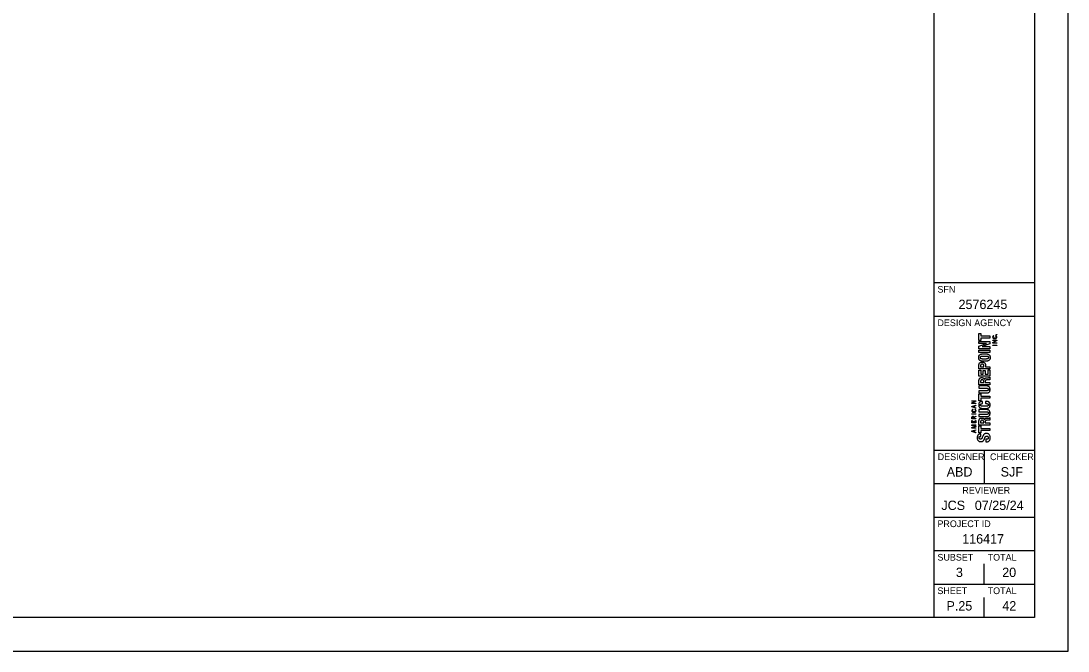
# Model space of a CAD drawing. Extents: x 0 to 34, y 0 to 22.
# Drawn here: x 18.37 to 34, y 0 to 9.41 of the extents above; entities that cross this region are included whole.
import ezdxf

# ---------------------------------------------------------------- set-up
doc = ezdxf.new("R2010")
doc.units = 0
for name, color, linetype in [('SH_Border', 7, 'Continuous'), ('SH_Cut_Line', 7, 'Continuous'), ('SH_Data', 7, 'Continuous')]:
    doc.layers.add(name, color=color, linetype=linetype)

msp = doc.modelspace()

# ---------------------------------------------------------------- linework, layer by layer
at = {"layer": 'SH_Border'}
for p, q in [((32, 0.5), (32, 21.5)), ((32, 5.5), (33.5, 5.5)), ((32, 5), (33.5, 5)), ((32, 3), (33.5, 3)), ((32.75, 3), (32.75, 2.5)), ((32, 2.5), (33.5, 2.5)), ((32, 2), (33.5, 2)), ((32, 1.5), (33.5, 1.5)), ((32, 1), (33.5, 1))]:
    msp.add_line(p, q, dxfattribs=at)
msp.add_lwpolyline([(1.5, 21.5), (33.5, 21.5), (33.5, 0.5), (1.5, 0.5)], close=True, dxfattribs=at)
at = {"layer": 'SH_Cut_Line'}
msp.add_lwpolyline([(0, 0), (34, 0), (34, 22), (0, 22)], close=True, dxfattribs=at)
at = {"layer": 'SH_Data'}
for p, q in [((32.75, 4), (32.75, 4)), ((32.75, 4), (32.75, 4)), ((32.75, 1), (32.75, 1.3)), ((32.75, 0.5), (32.75, 0.8)), ((32.375, 0.675), (32.375, 0.675))]:
    msp.add_line(p, q, dxfattribs=at)
for points in [[(32.67, 4.739), (32.697, 4.739), (32.697, 4.704), (32.833, 4.704), (32.833, 4.671), (32.697, 4.671), (32.697, 4.635), (32.67, 4.635), (32.67, 4.739)], [(32.935, 4.718), (32.927, 4.718), (32.927, 4.725), (32.935, 4.725), (32.935, 4.718)], [(32.67, 4.551), (32.781, 4.591), (32.781, 4.592), (32.67, 4.592), (32.67, 4.622), (32.833, 4.622), (32.833, 4.584), (32.719, 4.544), (32.719, 4.544), (32.833, 4.544), (32.833, 4.513), (32.67, 4.513), (32.67, 4.551)], [(32.875, 4.596), (32.875, 4.605), (32.925, 4.634), (32.925, 4.634), (32.875, 4.634), (32.875, 4.639), (32.935, 4.639), (32.935, 4.634), (32.88, 4.602), (32.88, 4.601), (32.935, 4.601), (32.935, 4.596), (32.875, 4.596)], [(32.875, 4.561), (32.875, 4.567), (32.935, 4.567), (32.935, 4.561), (32.875, 4.561)], [(32.833, 4.457), (32.67, 4.457), (32.67, 4.49), (32.833, 4.49), (32.833, 4.457)], [(32.833, 4.212), (32.67, 4.212), (32.67, 4.269)], [(32.694, 4.244), (32.743, 4.244), (32.743, 4.259)], [(32.694, 4.258), (32.694, 4.244)], [(32.768, 4.262), (32.768, 4.244), (32.833, 4.244), (32.833, 4.212)], [(32.67, 4.194), (32.697, 4.194), (32.697, 4.135), (32.735, 4.135), (32.735, 4.19), (32.762, 4.19), (32.762, 4.135), (32.806, 4.135), (32.806, 4.196), (32.833, 4.196), (32.833, 4.103), (32.67, 4.103), (32.67, 4.194)], [(32.832, 4.087), (32.833, 4.087), (32.833, 4.052)], [(32.833, 3.976), (32.67, 3.976), (32.67, 4.037)], [(32.694, 4.025), (32.694, 4.009)], [(32.694, 4.009), (32.741, 4.009), (32.741, 4.023)], [(32.752, 4.054), (32.752, 4.054)], [(32.764, 4.027), (32.764, 4.009), (32.833, 4.009), (32.833, 3.976)], [(32.816, 4.048), (32.784, 4.047)], [(32.67, 3.841), (32.697, 3.841), (32.697, 3.805), (32.833, 3.805), (32.833, 3.773), (32.697, 3.773), (32.697, 3.737), (32.67, 3.737), (32.67, 3.841)], [(32.565, 3.694), (32.565, 3.703), (32.615, 3.731), (32.615, 3.731), (32.565, 3.731), (32.565, 3.737), (32.625, 3.737), (32.625, 3.731), (32.569, 3.699), (32.569, 3.699), (32.625, 3.699), (32.625, 3.694), (32.565, 3.694)], [(32.625, 3.625), (32.565, 3.644), (32.565, 3.652), (32.625, 3.671), (32.625, 3.665), (32.605, 3.659), (32.605, 3.637), (32.625, 3.631), (32.625, 3.625)], [(32.601, 3.638), (32.601, 3.658), (32.569, 3.648), (32.569, 3.648), (32.601, 3.638)], [(32.565, 3.534), (32.565, 3.539), (32.625, 3.539), (32.625, 3.534), (32.565, 3.534)], [(32.596, 3.492), (32.625, 3.506), (32.625, 3.5), (32.597, 3.487), (32.597, 3.471), (32.625, 3.471), (32.625, 3.466), (32.565, 3.466), (32.565, 3.486)], [(32.625, 3.407), (32.565, 3.407), (32.565, 3.441), (32.569, 3.441), (32.569, 3.413), (32.591, 3.413), (32.591, 3.433), (32.596, 3.433), (32.596, 3.413), (32.62, 3.413), (32.62, 3.443), (32.625, 3.443), (32.625, 3.407)], [(32.569, 3.471), (32.593, 3.471), (32.593, 3.486)], [(32.569, 3.486), (32.569, 3.471)], [(32.752, 3.451), (32.752, 3.451)], [(32.816, 3.444), (32.784, 3.444)], [(32.832, 3.484), (32.833, 3.484), (32.833, 3.449)], [(32.625, 3.326), (32.565, 3.326), (32.565, 3.336), (32.615, 3.352), (32.615, 3.353), (32.565, 3.369), (32.565, 3.379), (32.625, 3.379), (32.625, 3.373), (32.569, 3.373), (32.569, 3.373), (32.625, 3.355), (32.625, 3.35), (32.569, 3.332), (32.569, 3.332), (32.625, 3.332), (32.625, 3.326)], [(32.625, 3.258), (32.565, 3.277), (32.565, 3.285), (32.625, 3.304), (32.625, 3.298), (32.605, 3.292), (32.605, 3.269), (32.625, 3.263), (32.625, 3.258)], [(32.601, 3.271), (32.601, 3.291), (32.569, 3.281), (32.569, 3.281), (32.601, 3.271)], [(32.833, 3.373), (32.67, 3.373), (32.67, 3.434)], [(32.67, 3.36), (32.697, 3.36), (32.697, 3.324), (32.833, 3.324), (32.833, 3.291), (32.697, 3.291), (32.697, 3.256), (32.67, 3.256), (32.67, 3.36)], [(32.694, 3.422), (32.694, 3.406)], [(32.694, 3.406), (32.741, 3.406), (32.741, 3.42)], [(32.764, 3.424), (32.764, 3.406), (32.833, 3.406), (32.833, 3.373)]]:
    msp.add_lwpolyline(points, dxfattribs=at)
for points in [[(32.893, 4.701), (32.889, 4.699), (32.885, 4.697), (32.883, 4.695), (32.88, 4.693), (32.879, 4.69), (32.879, 4.686), (32.879, 4.683), (32.88, 4.681), (32.881, 4.678), (32.882, 4.676), (32.884, 4.675), (32.887, 4.673), (32.889, 4.672), (32.892, 4.671), (32.895, 4.67), (32.898, 4.669), (32.902, 4.669), (32.905, 4.669), (32.909, 4.669), (32.912, 4.669), (32.915, 4.67), (32.919, 4.671), (32.921, 4.672), (32.924, 4.673), (32.926, 4.675), (32.928, 4.676), (32.929, 4.679), (32.931, 4.681), (32.931, 4.684), (32.931, 4.687), (32.931, 4.689), (32.931, 4.691), (32.93, 4.693), (32.929, 4.694), (32.928, 4.696), (32.927, 4.697), (32.926, 4.698), (32.924, 4.699), (32.922, 4.7), (32.921, 4.7), (32.919, 4.701), (32.917, 4.702), (32.917, 4.702), (32.918, 4.707), (32.918, 4.707), (32.92, 4.706), (32.923, 4.705), (32.925, 4.704), (32.927, 4.703), (32.929, 4.702), (32.931, 4.7), (32.932, 4.699), (32.934, 4.697), (32.934, 4.695), (32.935, 4.692), (32.936, 4.69), (32.936, 4.687), (32.936, 4.683), (32.935, 4.68), (32.934, 4.677), (32.932, 4.674), (32.93, 4.672), (32.927, 4.67), (32.925, 4.668), (32.921, 4.666), (32.918, 4.665), (32.914, 4.664), (32.91, 4.664), (32.905, 4.664), (32.901, 4.664), (32.896, 4.664), (32.893, 4.665), (32.889, 4.666), (32.886, 4.668), (32.883, 4.67), (32.88, 4.672), (32.878, 4.674), (32.877, 4.677), (32.875, 4.68), (32.875, 4.683), (32.875, 4.687), (32.875, 4.689), (32.875, 4.692), (32.876, 4.694), (32.877, 4.696), (32.878, 4.698), (32.88, 4.699), (32.881, 4.701), (32.883, 4.702), (32.885, 4.703), (32.887, 4.704), (32.889, 4.705), (32.892, 4.706), (32.892, 4.706), (32.893, 4.701), (32.893, 4.701)], [(32.751, 4.326), (32.739, 4.326), (32.727, 4.326), (32.717, 4.328), (32.706, 4.329), (32.697, 4.331), (32.69, 4.335), (32.682, 4.339), (32.677, 4.345), (32.672, 4.352), (32.668, 4.359), (32.666, 4.369), (32.666, 4.382), (32.666, 4.394), (32.668, 4.404), (32.672, 4.411), (32.677, 4.418), (32.682, 4.424), (32.69, 4.428), (32.697, 4.432), (32.706, 4.434), (32.717, 4.436), (32.727, 4.437), (32.739, 4.437), (32.751, 4.437), (32.758, 4.437), (32.764, 4.437), (32.771, 4.437)], [(32.751, 4.359), (32.762, 4.359), (32.771, 4.359), (32.779, 4.359), (32.787, 4.36), (32.793, 4.361), (32.798, 4.363), (32.803, 4.364), (32.806, 4.367), (32.808, 4.37), (32.81, 4.373), (32.812, 4.377), (32.812, 4.382), (32.812, 4.386), (32.81, 4.39), (32.808, 4.393), (32.806, 4.396), (32.803, 4.399), (32.798, 4.4), (32.793, 4.402), (32.787, 4.403), (32.779, 4.404), (32.771, 4.404), (32.762, 4.404), (32.751, 4.404), (32.74, 4.404), (32.731, 4.404), (32.723, 4.404), (32.716, 4.403), (32.709, 4.402), (32.704, 4.4), (32.7, 4.399), (32.696, 4.396), (32.694, 4.393), (32.692, 4.39), (32.691, 4.386), (32.691, 4.382), (32.691, 4.377), (32.692, 4.373), (32.694, 4.37), (32.696, 4.367), (32.7, 4.364), (32.704, 4.363), (32.709, 4.361), (32.716, 4.36), (32.723, 4.359), (32.731, 4.359), (32.74, 4.359), (32.751, 4.359)], [(32.771, 4.437), (32.776, 4.436), (32.781, 4.436), (32.785, 4.436), (32.796, 4.434), (32.805, 4.432), (32.812, 4.428), (32.82, 4.424), (32.825, 4.418), (32.83, 4.411), (32.834, 4.404), (32.836, 4.394), (32.836, 4.382), (32.836, 4.369), (32.834, 4.359), (32.83, 4.352), (32.825, 4.345), (32.82, 4.339), (32.812, 4.335), (32.805, 4.331), (32.796, 4.329), (32.785, 4.328), (32.775, 4.326), (32.763, 4.326), (32.751, 4.326)], [(32.67, 4.269), (32.67, 4.277), (32.671, 4.284), (32.674, 4.29), (32.677, 4.296), (32.68, 4.3), (32.685, 4.304), (32.689, 4.307), (32.695, 4.31), (32.701, 4.312), (32.706, 4.313), (32.712, 4.314), (32.719, 4.314), (32.727, 4.314), (32.734, 4.313), (32.741, 4.31), (32.747, 4.308), (32.752, 4.304), (32.756, 4.3), (32.76, 4.295), (32.763, 4.29), (32.765, 4.283), (32.767, 4.277), (32.768, 4.27), (32.768, 4.262)], [(32.743, 4.259), (32.743, 4.266), (32.741, 4.271), (32.737, 4.275), (32.733, 4.279), (32.727, 4.281), (32.719, 4.281), (32.711, 4.281), (32.705, 4.279), (32.7, 4.276), (32.696, 4.272), (32.694, 4.266), (32.694, 4.258)], [(32.67, 4.037), (32.67, 4.051), (32.673, 4.062), (32.68, 4.069), (32.687, 4.077), (32.698, 4.081), (32.712, 4.081), (32.723, 4.081), (32.732, 4.079), (32.739, 4.074), (32.745, 4.07), (32.75, 4.063), (32.752, 4.054)], [(32.752, 4.054), (32.753, 4.059), (32.755, 4.064), (32.757, 4.067), (32.759, 4.071), (32.762, 4.073), (32.766, 4.075), (32.769, 4.077), (32.774, 4.078), (32.78, 4.079), (32.786, 4.08), (32.794, 4.08), (32.802, 4.08), (32.811, 4.08), (32.818, 4.081), (32.822, 4.082), (32.827, 4.082), (32.83, 4.084), (32.832, 4.087)], [(32.67, 3.885), (32.67, 3.885), (32.783, 3.885), (32.783, 3.885), (32.787, 3.885), (32.791, 3.885), (32.795, 3.886), (32.798, 3.887), (32.801, 3.888), (32.803, 3.889), (32.806, 3.89), (32.808, 3.892), (32.809, 3.895), (32.811, 3.897), (32.812, 3.901), (32.812, 3.904), (32.812, 3.908), (32.811, 3.911), (32.809, 3.914), (32.808, 3.917), (32.806, 3.918), (32.803, 3.92), (32.801, 3.921), (32.798, 3.922), (32.795, 3.923), (32.791, 3.923), (32.787, 3.924), (32.783, 3.924), (32.783, 3.924), (32.67, 3.924), (32.67, 3.924), (32.67, 3.924), (32.67, 3.957), (32.67, 3.957), (32.67, 3.957), (32.783, 3.957), (32.783, 3.957), (32.794, 3.957), (32.802, 3.955), (32.809, 3.952), (32.816, 3.949), (32.821, 3.945), (32.825, 3.941), (32.829, 3.936), (32.832, 3.93), (32.834, 3.924), (32.835, 3.918), (32.836, 3.911), (32.836, 3.904), (32.836, 3.898), (32.835, 3.891), (32.834, 3.885), (32.833, 3.879), (32.83, 3.873), (32.826, 3.868), (32.822, 3.863), (32.817, 3.86), (32.81, 3.857), (32.803, 3.854), (32.794, 3.852), (32.783, 3.852), (32.783, 3.852), (32.67, 3.852), (32.67, 3.852), (32.67, 3.852), (32.67, 3.885), (32.67, 3.885)], [(32.741, 4.023), (32.741, 4.031), (32.739, 4.037), (32.735, 4.042), (32.732, 4.046), (32.725, 4.048), (32.717, 4.048), (32.702, 4.048), (32.694, 4.04), (32.694, 4.025)], [(32.784, 4.047), (32.778, 4.046), (32.773, 4.045), (32.769, 4.042), (32.766, 4.039), (32.764, 4.034), (32.764, 4.027)], [(32.833, 4.052), (32.831, 4.05), (32.828, 4.049), (32.825, 4.049), (32.822, 4.048), (32.819, 4.048), (32.816, 4.048)], [(32.582, 3.601), (32.578, 3.6), (32.575, 3.598), (32.572, 3.595), (32.57, 3.593), (32.569, 3.59), (32.569, 3.586), (32.569, 3.583), (32.569, 3.581), (32.571, 3.579), (32.572, 3.577), (32.574, 3.575), (32.576, 3.574), (32.579, 3.572), (32.581, 3.571), (32.585, 3.57), (32.588, 3.57), (32.591, 3.569), (32.595, 3.569), (32.598, 3.569), (32.602, 3.57), (32.605, 3.57), (32.608, 3.571), (32.611, 3.572), (32.613, 3.574), (32.616, 3.575), (32.618, 3.577), (32.619, 3.579), (32.62, 3.581), (32.621, 3.584), (32.621, 3.587), (32.621, 3.589), (32.62, 3.591), (32.62, 3.593), (32.619, 3.595), (32.618, 3.596), (32.617, 3.597), (32.615, 3.598), (32.614, 3.599), (32.612, 3.6), (32.61, 3.601), (32.608, 3.602), (32.606, 3.602), (32.606, 3.602), (32.607, 3.607), (32.607, 3.607), (32.61, 3.607), (32.612, 3.606), (32.615, 3.605), (32.617, 3.604), (32.619, 3.602), (32.62, 3.601), (32.622, 3.599), (32.623, 3.597), (32.624, 3.595), (32.625, 3.593), (32.625, 3.59), (32.625, 3.587), (32.625, 3.583), (32.625, 3.58), (32.623, 3.577), (32.622, 3.574), (32.62, 3.572), (32.617, 3.57), (32.614, 3.568), (32.611, 3.567), (32.607, 3.566), (32.604, 3.565), (32.599, 3.564), (32.595, 3.564), (32.59, 3.564), (32.586, 3.565), (32.582, 3.566), (32.579, 3.567), (32.575, 3.568), (32.573, 3.57), (32.57, 3.572), (32.568, 3.574), (32.566, 3.577), (32.565, 3.58), (32.564, 3.583), (32.564, 3.587), (32.564, 3.59), (32.565, 3.592), (32.566, 3.594), (32.566, 3.596), (32.568, 3.598), (32.569, 3.599), (32.571, 3.601), (32.572, 3.602), (32.575, 3.603), (32.577, 3.604), (32.579, 3.605), (32.581, 3.606), (32.581, 3.606), (32.582, 3.601), (32.582, 3.601)], [(32.725, 3.693), (32.713, 3.693), (32.704, 3.692), (32.699, 3.689), (32.693, 3.686), (32.691, 3.681), (32.691, 3.674), (32.691, 3.67), (32.692, 3.666), (32.694, 3.663), (32.696, 3.661), (32.7, 3.659), (32.705, 3.657), (32.71, 3.656), (32.716, 3.655), (32.724, 3.654), (32.732, 3.653), (32.742, 3.653), (32.753, 3.653), (32.766, 3.653), (32.776, 3.653), (32.783, 3.654), (32.791, 3.655), (32.797, 3.656), (32.801, 3.658), (32.805, 3.66), (32.808, 3.662), (32.809, 3.665), (32.811, 3.668), (32.812, 3.671), (32.812, 3.674), (32.812, 3.677), (32.811, 3.68), (32.81, 3.682), (32.809, 3.685), (32.807, 3.687), (32.804, 3.689), (32.801, 3.691), (32.797, 3.692), (32.792, 3.693), (32.786, 3.694), (32.779, 3.695), (32.77, 3.695), (32.77, 3.695), (32.77, 3.728), (32.77, 3.728), (32.779, 3.728), (32.787, 3.727), (32.795, 3.726), (32.803, 3.724), (32.81, 3.722), (32.816, 3.718), (32.822, 3.714), (32.827, 3.709), (32.831, 3.702), (32.834, 3.696), (32.836, 3.687), (32.836, 3.676), (32.836, 3.663), (32.834, 3.654), (32.83, 3.646), (32.825, 3.639), (32.82, 3.633), (32.812, 3.629), (32.805, 3.626), (32.796, 3.623), (32.785, 3.622), (32.775, 3.621), (32.763, 3.62), (32.751, 3.62), (32.739, 3.62), (32.727, 3.621), (32.717, 3.622), (32.706, 3.623), (32.697, 3.626), (32.69, 3.629), (32.682, 3.633), (32.677, 3.639), (32.672, 3.646), (32.668, 3.654), (32.666, 3.663), (32.666, 3.676), (32.666, 3.688), (32.668, 3.697), (32.672, 3.704), (32.676, 3.71), (32.681, 3.715), (32.687, 3.719), (32.692, 3.722), (32.699, 3.724), (32.706, 3.725), (32.712, 3.726), (32.719, 3.726), (32.725, 3.726), (32.725, 3.726), (32.725, 3.693), (32.725, 3.693)], [(32.67, 3.532), (32.67, 3.532), (32.783, 3.532), (32.783, 3.532), (32.787, 3.532), (32.791, 3.533), (32.795, 3.533), (32.798, 3.534), (32.801, 3.535), (32.803, 3.536), (32.806, 3.538), (32.808, 3.54), (32.809, 3.542), (32.811, 3.545), (32.812, 3.548), (32.812, 3.552), (32.812, 3.556), (32.811, 3.559), (32.809, 3.561), (32.808, 3.564), (32.806, 3.566), (32.803, 3.567), (32.801, 3.569), (32.798, 3.57), (32.795, 3.57), (32.791, 3.571), (32.787, 3.571), (32.783, 3.571), (32.783, 3.571), (32.67, 3.571), (32.67, 3.571), (32.67, 3.571), (32.67, 3.604), (32.67, 3.604), (32.67, 3.604), (32.783, 3.604), (32.783, 3.604), (32.794, 3.604), (32.802, 3.602), (32.809, 3.6), (32.816, 3.597), (32.821, 3.593), (32.825, 3.588), (32.829, 3.583), (32.832, 3.577), (32.834, 3.571), (32.835, 3.565), (32.836, 3.558), (32.836, 3.552), (32.836, 3.545), (32.835, 3.539), (32.834, 3.532), (32.833, 3.526), (32.83, 3.521), (32.826, 3.516), (32.822, 3.511), (32.817, 3.507), (32.81, 3.504), (32.803, 3.501), (32.794, 3.5), (32.783, 3.5), (32.783, 3.5), (32.67, 3.5), (32.67, 3.5), (32.67, 3.5), (32.67, 3.532), (32.67, 3.532)], [(32.565, 3.486), (32.565, 3.492), (32.566, 3.496), (32.569, 3.499), (32.572, 3.503), (32.576, 3.504), (32.581, 3.504), (32.585, 3.504), (32.588, 3.503), (32.591, 3.501), (32.593, 3.499), (32.595, 3.496), (32.596, 3.492)], [(32.593, 3.486), (32.593, 3.49), (32.592, 3.493), (32.59, 3.495), (32.588, 3.497), (32.585, 3.499), (32.581, 3.499), (32.577, 3.499), (32.575, 3.498), (32.573, 3.495), (32.57, 3.493), (32.569, 3.49), (32.569, 3.486)], [(32.67, 3.434), (32.67, 3.448), (32.673, 3.458), (32.68, 3.466), (32.687, 3.474), (32.698, 3.478), (32.712, 3.478), (32.723, 3.478), (32.732, 3.475), (32.739, 3.471), (32.745, 3.467), (32.75, 3.46), (32.752, 3.451)], [(32.741, 3.42), (32.741, 3.428), (32.739, 3.434), (32.735, 3.438), (32.732, 3.443), (32.725, 3.445), (32.717, 3.445), (32.702, 3.445), (32.694, 3.437), (32.694, 3.422)], [(32.752, 3.451), (32.753, 3.456), (32.755, 3.461), (32.757, 3.464), (32.759, 3.467), (32.762, 3.47), (32.766, 3.472), (32.769, 3.474), (32.774, 3.475), (32.78, 3.476), (32.786, 3.476), (32.794, 3.477), (32.802, 3.477), (32.811, 3.477), (32.818, 3.478), (32.822, 3.478), (32.827, 3.479), (32.83, 3.481), (32.832, 3.484)], [(32.784, 3.444), (32.778, 3.443), (32.773, 3.442), (32.769, 3.439), (32.766, 3.436), (32.764, 3.431), (32.764, 3.424)], [(32.833, 3.449), (32.831, 3.447), (32.828, 3.446), (32.825, 3.445), (32.822, 3.445), (32.819, 3.445), (32.816, 3.444)], [(32.775, 3.161), (32.775, 3.161), (32.781, 3.161), (32.781, 3.161), (32.785, 3.161), (32.789, 3.162), (32.793, 3.162), (32.796, 3.163), (32.799, 3.164), (32.801, 3.166), (32.804, 3.168), (32.806, 3.171), (32.807, 3.174), (32.809, 3.177), (32.809, 3.181), (32.809, 3.186), (32.809, 3.192), (32.807, 3.197), (32.804, 3.201), (32.8, 3.206), (32.794, 3.208), (32.786, 3.208), (32.782, 3.208), (32.779, 3.208), (32.776, 3.207), (32.773, 3.205), (32.77, 3.204), (32.767, 3.201), (32.765, 3.198), (32.763, 3.195), (32.761, 3.191), (32.759, 3.187), (32.757, 3.181), (32.755, 3.175), (32.752, 3.167), (32.749, 3.16), (32.745, 3.154), (32.742, 3.147), (32.738, 3.142), (32.734, 3.138), (32.73, 3.134), (32.725, 3.131), (32.719, 3.129), (32.713, 3.128), (32.706, 3.127), (32.699, 3.127), (32.68, 3.127), (32.667, 3.132), (32.658, 3.142), (32.649, 3.152), (32.644, 3.166), (32.644, 3.184), (32.644, 3.192), (32.645, 3.2), (32.647, 3.207), (32.649, 3.214), (32.651, 3.22), (32.656, 3.225), (32.66, 3.23), (32.665, 3.234), (32.671, 3.237), (32.677, 3.24), (32.685, 3.241), (32.694, 3.241), (32.694, 3.241), (32.699, 3.241), (32.699, 3.241), (32.699, 3.241), (32.699, 3.205), (32.699, 3.205), (32.69, 3.205), (32.683, 3.204), (32.679, 3.201), (32.674, 3.197), (32.671, 3.192), (32.671, 3.185), (32.671, 3.181), (32.672, 3.178), (32.673, 3.175), (32.675, 3.172), (32.676, 3.17), (32.678, 3.168), (32.68, 3.167), (32.682, 3.165), (32.685, 3.165), (32.688, 3.164), (32.69, 3.164), (32.693, 3.164), (32.699, 3.164), (32.704, 3.165), (32.707, 3.168), (32.711, 3.17), (32.715, 3.175), (32.718, 3.183), (32.718, 3.183), (32.731, 3.212), (32.731, 3.212), (32.734, 3.219), (32.737, 3.225), (32.74, 3.229), (32.744, 3.234), (32.747, 3.237), (32.751, 3.24), (32.755, 3.243), (32.76, 3.245), (32.764, 3.246), (32.769, 3.247), (32.774, 3.247), (32.78, 3.247), (32.799, 3.247), (32.814, 3.242), (32.823, 3.23), (32.832, 3.219), (32.837, 3.203), (32.837, 3.183), (32.837, 3.162), (32.832, 3.147), (32.823, 3.138), (32.813, 3.128), (32.8, 3.124), (32.783, 3.124), (32.783, 3.124), (32.775, 3.124), (32.775, 3.124), (32.775, 3.124), (32.775, 3.161), (32.775, 3.161)]]:
    msp.add_open_spline(points, degree=3, dxfattribs=at)

# ---------------------------------------------------------------- texts
for s, height, p in [('SFN', 0.1, (32.05, 5.35)), ('2576245', 0.14, (32.365, 5.105)), ('DESIGN AGENCY', 0.1, (32.05, 4.85)), ('DESIGNER', 0.1, (32.054, 2.85)), ('CHECKER', 0.1, (32.835, 2.85)), ('ABD', 0.14, (32.188, 2.605)), ('SJF', 0.14, (32.994, 2.605)), ('REVIEWER', 0.1, (32.422, 2.35)), ('JCS', 0.14, (32.109, 2.105)), ('07/25/24', 0.14, (32.608, 2.105)), ('PROJECT ID', 0.1, (32.05, 1.85)), ('116417', 0.14, (32.42, 1.605)), ('SUBSET', 0.1, (32.05, 1.35)), ('TOTAL', 0.1, (32.8, 1.35)), ('3', 0.14, (32.326, 1.105)), ('20', 0.14, (33.017, 1.105)), ('SHEET', 0.1, (32.05, 0.85)), ('TOTAL', 0.1, (32.8, 0.85)), ('P.25', 0.14, (32.185, 0.605)), ('42', 0.14, (33.019, 0.605))]:
    msp.add_text(s, height=height, dxfattribs=at).set_placement(p)

doc.saveas('drawing.dxf')
